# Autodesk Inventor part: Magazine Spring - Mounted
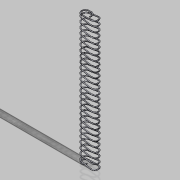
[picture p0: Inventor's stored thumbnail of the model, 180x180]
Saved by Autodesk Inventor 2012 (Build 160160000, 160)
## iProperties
Created: 2011-12
Part Number: Magazine Spring - Mounted
Material: Carbon Steel
Document SubType Name: Modeling
Designer: Michael Høgh
Density: 7.87 g/cm^3
Project: Sten MK II
Engineer: MH Vaaben Teknik
Mass: 25.3587 g
Surface Area: 85.9599 cm^2
Volume: 3.22219 cm^3
Company: MH Vaaben Teknik
Category: Sten MK II Magazine Spring
GlobalPropertyList: <PropertyList/>
Author: Michael Høgh
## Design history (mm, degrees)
sketch "Sketch1"
  geometry: L1 (-7.35, 5.25)-(7.66, 5.747); A1 r 5.25 centre (-7.35, 0) between (-7.35, 5.25) and (-7.35, -5.25); A2 r 5.75 centre (7.85, 0) between (7.85, -5.75) and (7.66, 5.747); A3 r 4 centre (-7.35, -1.25) between (-7.35, -5.25) and (-3.35, -1.25); 2 further points
  constraints: 6 point on circle, 3 centre point, 2 end point, 2 tangent, 1 coincident
  dimensions: "d0" = 10.5 diameter of A1; "d1" = 11.5 diameter of A2; "d2" = 15.2 distance of A2.centre A1.centre; "d3" = 7.35 distance of point (0, 0) A1.centre; "d4" = 8 diameter of A3; "d7" = 0 vertical distance of point (0, 0) A2.centre
sketch "3D Sketch1" dims "d8" = 20.9355, "d66" = 7.9985, "d67" = 7.9985, "d68" = 7.9985, "d69" = 7.9985, "d70" = 7.9985, "d71" = 7.9985, "d72" = 7.9985, "d73" = 7.9985, "d74" = 7.9985, "d75" = 7.9985, "d76" = 7.9985, "d77" = 7.9985, "d78" = 7.9985, "d79" = 7.9985, "d80" = 7.9985, "d81" = 7.9985, "d82" = 7.9985, "d83" = 7.9985, "d84" = 7.9985, "d85" = 7.9985, "d86" = 7.9985, "d87" = 7.9985, "d88" = 7.9985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
workplane "Work Plane2"
sketch "Sketch4"
  geometry: C1 r 0.75 at (0, 0); 1 further point
  constraints: 1 centre point
  dimensions: "d279" = 1.5 diameter of C1
sweep "Sweep4" sketch "Sketch4" dims "d316" = 0
body "Solid4"
